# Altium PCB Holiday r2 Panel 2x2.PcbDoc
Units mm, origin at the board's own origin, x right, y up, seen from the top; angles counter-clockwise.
Board outline 134 x 160 mm, 4 copper layers (Top Layer, Mid-Layer 1, Internal Plane 1, Bottom Layer), stack 1.582 mm thick; 0 components, 0 nets, 18 pads, 0 vias.
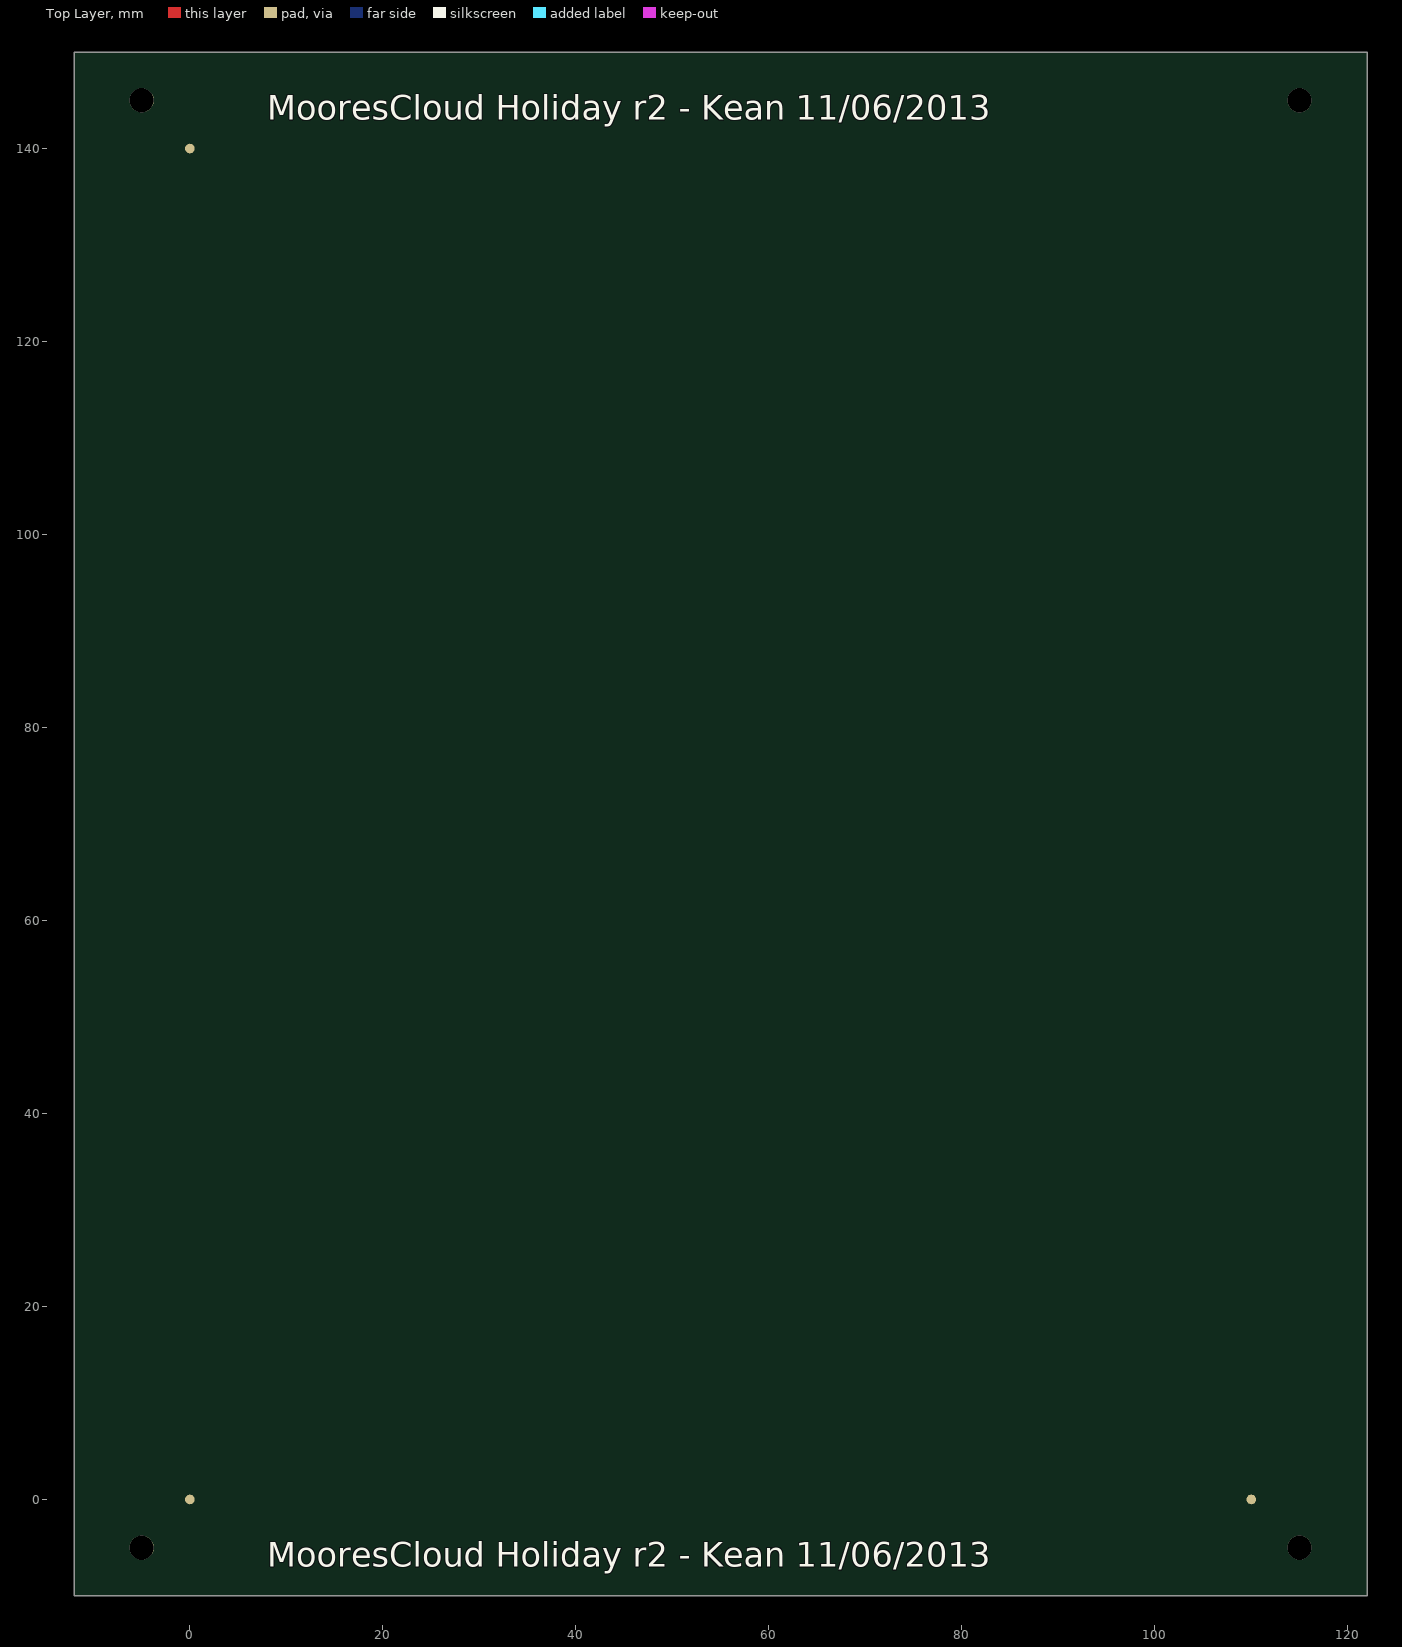
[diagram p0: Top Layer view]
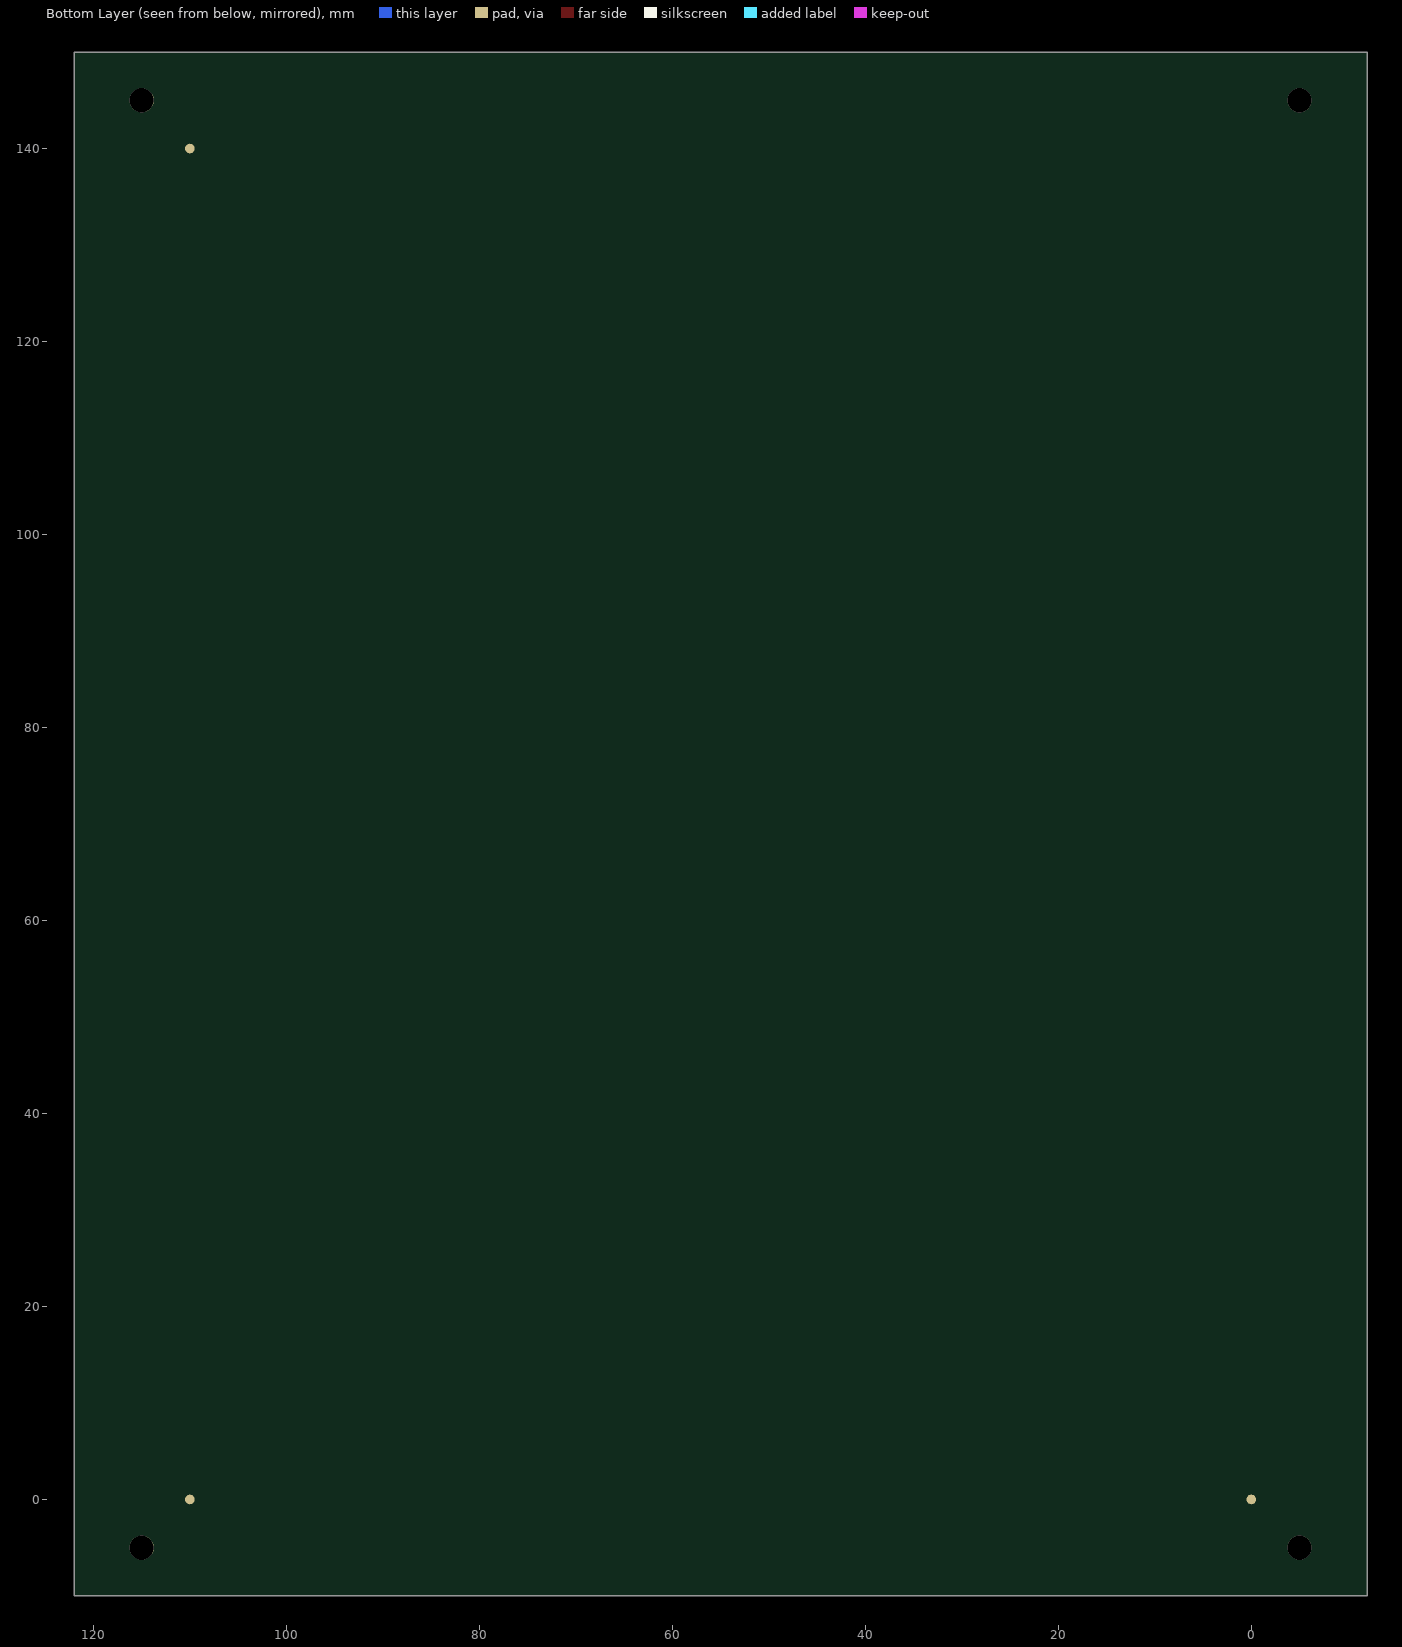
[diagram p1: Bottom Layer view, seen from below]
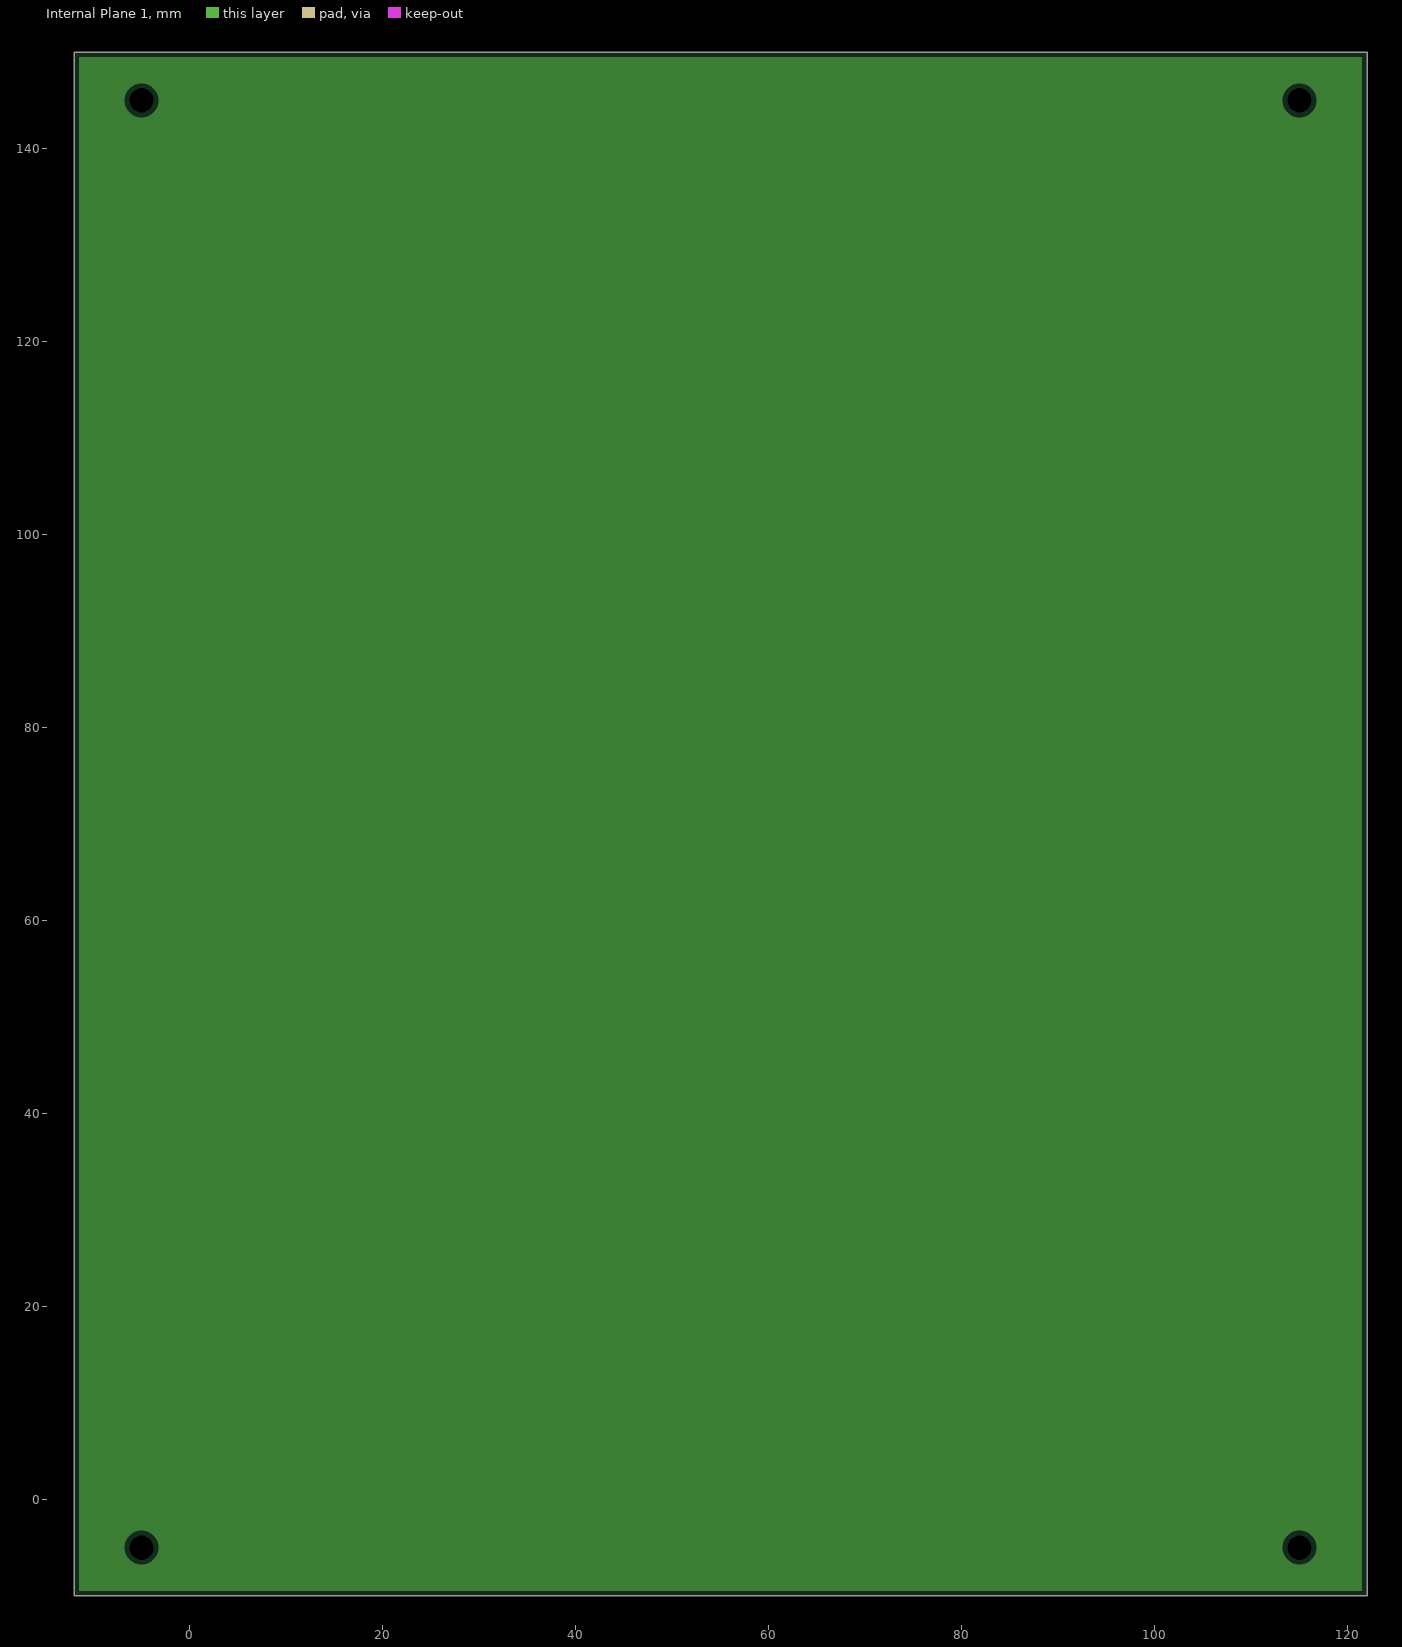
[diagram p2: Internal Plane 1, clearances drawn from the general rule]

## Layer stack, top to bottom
Top Layer: signal copper 0.0356
Dielectric: prepreg 0.32, FR-4, Dk 4.8
Mid-Layer 1: signal copper 0.0356
Dielectric: core 0.8, FR-4, Dk 4.8
Internal Plane 1: plane copper 0.0356
Dielectric: prepreg 0.32, FR-4, Dk 4.8
Bottom Layer: signal copper 0.0356

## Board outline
-12,-10 -12,150 122,150 122,-10

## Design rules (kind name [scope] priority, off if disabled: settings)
Clearance [All] p1: gap=0.254
PlaneClearance [All] p1: clearance=0.508
PlaneConnect [All] p1: planeconnectstyle=Relief reliefexpansion=0.508 reliefentries=4 reliefconductorwidth=0.254 reliefairgap=0.254
PolygonConnect [All] p1: connectstyle=Relief reliefconductorwidth=0.254 reliefentries=4 polygonreliefangle="90 Angle" airgapwidth=0.254
RoutingVias [All] p1: holewidth=0.711 width=1.27 viastyle="Through Hole" minholewidth=0.711 minwidth=1.27 maxholewidth=0.711 maxwidth=1.27
SolderMaskExpansion [All] p1: expansion=0.102
Width [All] p1: maxlimit=0.254 minlimit=0.254 preferedwidth=0.254
26 further rules are at their usual default settings.

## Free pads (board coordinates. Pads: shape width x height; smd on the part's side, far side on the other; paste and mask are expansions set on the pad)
  round 0 hole 2.5 unplated: 0(-5,-5) 0(-5,145) 0(115,-5) 0(115,145)
  round 2.5 smd paste+0 mask+0: 0(-5,-5) 0(-5,145) 0(115,-5) 0(115,145)
  round 2.5 smd far side paste+0 mask+0: 0(-5,-5) 0(-5,145) 0(115,-5) 0(115,145)
  round 1 smd far side paste-1 mask+1: FID1(0,0) FID1(110,0) FID1(110,140)
  round 1 smd paste-1 mask+1: FID1(0,0) FID1(0,140) FID1(110,0)

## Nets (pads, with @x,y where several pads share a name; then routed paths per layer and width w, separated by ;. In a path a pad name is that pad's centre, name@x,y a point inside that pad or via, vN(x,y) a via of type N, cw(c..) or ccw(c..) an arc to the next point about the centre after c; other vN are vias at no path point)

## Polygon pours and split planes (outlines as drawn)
no net on Internal Plane 1 (split plane): 121.49,-9.49 -11.49,-9.49 -11.49,149.49 121.49,149.49

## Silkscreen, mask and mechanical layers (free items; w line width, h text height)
Top Overlay:
  text "MooresCloud Holiday r2 - Kean 11/06/2013" at 8,143 h2.54
  text "MooresCloud Holiday r2 - Kean 11/06/2013" at 8,-7 h2.54
Mechanical 5:
  lines w0.1: -12,-10 122,-10 122,150 -12,150 -12,-10
  lines w0.2: -12,3 122,3 ; -12,70 122,70 ; -12,137 122,137 ; 55,-10 55,150
Drill Drawing:
  lines w0.1: 159.5,3.7 217.75,3.7 ; 159.5,5.7 217.75,5.7 ; 159.5,14.45 217.75,14.45 ; 159.5,16.45 217.75,16.45 ; 159.5,18.45 217.75,18.45 ; 159.5,20.45 217.75,20.45 ; 159.5,22.45 217.75,22.45 ; 159.5,24.45 217.75,24.45 ; 159.5,26.45 217.75,26.45 ; 159.5,28.45 217.75,28.45 ; 172,1.7 172,7.95 ; 172,12.45 172,30.45 ; 159.5,1.7 217.75,1.7 217.75,7.95 159.5,7.95 159.5,1.7 ; 159.5,12.45 159.5,30.45 217.75,30.45 217.75,12.45 159.5,12.45
  lines w0.15: 160.524,81.6 215.576,81.6 ; 160.524,84.415 215.576,84.415 ; 159,63.9 ccw(c159.9,63.9) 159.9,63 216.2,63 ccw(c216.2,63.9) 217.1,63.9 217.1,86.8 ccw(c216.2,86.8) 216.2,87.7 159.9,87.7 ccw(c159.9,86.8) 159,86.8 159,63.9
  text "Layer Stack Up Detail for: Holiday r1.PcbDoc" at 160.524,85.173 h1.2
  text "Layer" at 160.524,83.365 h0.65
  text "Gerber" at 186.095,83.365 h0.65
  text "Dielectric" at 203.022,83.365 h0.65
  text "Name" at 160.524,82.065 h0.65
  text "Document" at 186.095,82.065 h0.65
  text "Material" at 203.022,82.065 h0.65
  text "Top Solder Mask" at 160.524,80.239 h0.9
  text "(.GTS)" at 186.095,80.239 h0.9
  text "Solder Resist" at 203.022,80.239 h0.9
  text "Top Layer" at 160.524,77.666 h0.9
  text "(.GTL)" at 186.095,77.666 h0.9
  text "FR-4" at 203.022,76.379 h0.9
  text "Mid-Layer 1" at 160.524,75.093 h0.9
  text "(.G1)" at 186.095,75.093 h0.9
  text "FR-4" at 203.022,73.806 h0.9
  text "InternalPlane1" at 160.524,72.52 h0.9
  text "(.GP1)" at 186.095,72.52 h0.9
  text "FR-4" at 203.022,71.233 h0.9
  text "Bottom Layer" at 160.524,69.947 h0.9
  text "(.GBL)" at 186.095,69.947 h0.9
  text "Bottom Solder Mask" at 160.524,67.374 h0.9
  text "(.GBS)" at 186.095,67.374 h0.9
  text "Solder Resist" at 203.022,67.374 h0.9
  text ".legend" at 160.75,35.7 h1
  text "BOARD SIZE:" at 160,28.95 h1
  text "134.00mm x 160.00mm" at 173,28.95 h1
  text "LAYERS:" at 160,26.95 h1
  text "4" at 173,26.95 h1
  text "MATERIAL:" at 160,24.95 h1
  text "FR4 1.6mm" at 173,24.95 h1
  text "COPPER:" at 160,22.95 h1
  text "35um (after plating)" at 173,22.95 h1
  text "PTH PLATING:" at 160,20.95 h1
  text "20um (minimum)" at 173,20.95 h1
  text "FINISH:" at 160,18.95 h1
  text "ROHS ENIG or HAL ?" at 173,18.95 h1
  text "OVERLAY:" at 160,16.95 h1
  text "White, 2 sides" at 173,16.95 h1
  text "SOLDER MASK:" at 160,14.95 h1
  text "Green LPI, 2 sides" at 173,14.95 h1
  text "PROFILING:" at 160,12.95 h1
  text "V-Groove" at 173,12.95 h1
  text "FILE NAME:" at 160,6.2 h1
  text ".Pcb_File_Name_No_Path" at 173,6.2 h1
  text "LAYER:" at 160,4.2 h1
  text ".Plot_File_Name" at 173,4.2 h1
  text "PRINT DATE:" at 160,2.2 h1
  text ".Print_Date" at 173,2.2 h1

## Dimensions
125,3 to 133,3 on Mechanical 5
125,70 to 133,70 on Mechanical 5
125,137 to 133,137 on Mechanical 5
55,152 to 55,160 on Mechanical 5
-13,3 to -16,70 on Mechanical 5
-15,-10 to -13,3 on Mechanical 5
-12,-11 to 122,-11 on Mechanical 5
-13,-10 to -13,150 on Mechanical 5
-13,-5 to -13,-10 on Mechanical 5
-12,-11 to 55,-12 on Mechanical 5
-5,-11 to -12,-11 on Mechanical 5

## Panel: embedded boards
"Holiday r2.PcbDoc" at -12,3, 2 rows x 2 columns, spacing 67 x 67, rotation 0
